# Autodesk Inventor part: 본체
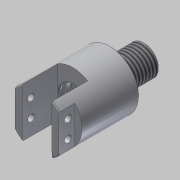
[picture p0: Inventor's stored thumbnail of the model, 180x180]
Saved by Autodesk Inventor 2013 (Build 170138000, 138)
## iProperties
Created: 2019-02
Part Number: 본체
Material: 알루미늄 6061
Document SubType Name: Modeling
Designer: dgall
Density: 2.71 g/cm^3
Mass: 345.865 g
Surface Area: 291.141 cm^2
Volume: 127.625 cm^3
Author: dgall
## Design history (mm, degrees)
sketch "스케치5"
  geometry: C1 r 29 at (0, 0); 1 further point
  constraints: 1 centre point, 1 coincident
  dimensions: "d12" = 58 diameter of C1
extrude "돌출3" new body sketch "스케치5" stored distance "d14" = 74; taper "d15" = 0 deg
sketch "스케치6"
  geometry: L1 (14.984, 24.829)-(15.016, -24.81); L2 (-14.984, -24.829)-(-15.016, 24.81); A1 r 29 centre (0, 0) between (-15.016, 24.81) and (15.016, -24.81) reference; A2 r 29 centre (0, 0) between (-15.016, 24.81) and (15.016, -24.81) reference; A3 r 29 centre (0, 0) between (-14.984, -24.829) and (15.016, -24.81); A4 r 29 centre (0, 0) between (14.984, 24.829) and (-15.016, 24.81)
  constraints: 11 point on circle, 4 end point, 2 centre point, 1 coincident, 1 parallel
  dimensions: "d17" = 30 distance between parallel lines of L1 L2; "d19" = 15 distance from line of A1.centre L2; "d20" = 24.80968 vertical distance of L1.end A1.centre
extrude "돌출4" cut sketch "스케치6" distance "d21" = 36; taper "d22" = 0 deg
node "작업 평면3"
sketch "스케치7"
  geometry: L1 (-37, 24.81)-(-37, -24.829) reference; L2 (-37, 24.81)-(-21, 24.81); L3 (-21, 24.81)-(-21, -24.829); L4 (-21, -24.829)-(-37, -24.829); L5 (-37, -24.829)-(-37, 24.81); 1 further point
  constraints: 8 end point, 2 parallel, 1 horizontal, 1 perpendicular, 1 point on line
  dimensions: "d24" = 16 distance between parallel lines of L3 L1; "d25" = 0 distance from line of L1.start L2; "d26" = 0 distance from line of L1.end L4
extrude "돌출5" cut sketch "스케치7" distance "d27" = 36; taper "d28" = 0 deg
sketch "스케치9"
  geometry: L1 (-1, -24.829)-(-1, 24.81) reference; L2 (-1, -0.01)-(36.922, -0.01); L3 (-1, -0.01)-(-1, 13.99); L4 (-1, 13.99)-(1.65, 13.99); L5 (1.65, 13.99)-(1.65, 16.19); L6 (2.45, 16.99)-(5.55, 16.99); L7 (6.35, 16.19)-(6.35, 13.99); L8 (6.35, 13.99)-(10.65, 13.99); L9 (10.65, 13.99)-(10.65, 16.19); L10 (11.45, 16.99)-(14.55, 16.99); L11 (15.35, 16.19)-(15.35, 13.99); L12 (15.35, 13.99)-(19, 13.99); L13 (19, 13.99)-(19, 15.99); L14 (4, 16.99)-(4, -0.01); L15 (13, 16.99)-(13, -0.01); L16 (19, 15.99)-(26, 15.99); L17 (26, 15.99)-(26, -0.01); A1 r 0.8 centre (2.45, 16.19) between (2.45, 16.99) and (1.65, 16.19); A2 r 0.8 centre (5.55, 16.19) between (6.35, 16.19) and (5.55, 16.99); A3 r 0.8 centre (11.45, 16.19) between (11.45, 16.99) and (10.65, 16.19); A4 r 0.8 centre (14.55, 16.19) between (15.35, 16.19) and (14.55, 16.99); 5 further points
  constraints: 32 end point, 12 point on line, 8 point on circle, 8 tangent, 7 perpendicular, 6 parallel, 4 centre point, 3 midpoint, 2 collinear, 2 equal radius
  dimensions: "d32" = 28 diameter of L4 L2; "d33" = 34 diameter of L6 L2; "d34" = 5 distance between parallel lines of L14 L3; "d35" = 4.7 distance between parallel lines of L7 L5; "d36" = 28 diameter of L8 L2; "d37" = 4.7 distance between parallel lines of L11 L9; "d38" = 9 distance between parallel lines of L15 L14; "d39" = 34 diameter of L10 L2; "d40" = 28 diameter of L12 L2; "d41" = 32 diameter of L16 L2; "d42" = 7 distance between parallel lines of L17 L13; "d44" = 20 distance between parallel lines of L13 L1; "d70" = 0.8 radius of A1; "d71" = 0.8 radius of A2
revolve "회전1" sketch "스케치9" stored, may be unused: angle "d45" = 90 deg
sketch "스케치10"
  geometry: C1 r 29 at (0, 0) reference; C2 r 14 at (0, 0)
  constraints: 1 centre point, 1 coincident
  dimensions: "d46" = 28 diameter of C2
extrude "돌출6" join sketch "스케치10" distance "d48" = 5; taper "d49" = 0 deg
sketch "스케치11"
  geometry: C1 r 14 at (0, 0) reference; C2 r 15 at (0, 0)
  constraints: 1 centre point, 1 coincident
  dimensions: "d50" = 30 diameter of C2
extrude "돌출7" join sketch "스케치11" distance "d52" = 29; taper "d53" = 0 deg
sketch "스케치12"
  geometry: C1 r 15 at (0, 0) reference; C2 r 7 at (0, 0)
  constraints: 1 centre point, 1 coincident
  dimensions: "d54" = 14 diameter of C2
extrude "돌출8" cut sketch "스케치12" distance "d56" = 22; taper "d57" = 0 deg
sketch "스케치13"
  geometry: C1 r 7 at (0, 0) reference; C2 r 4 at (0, 0)
  constraints: 1 centre point, 1 coincident
  dimensions: "d58" = 8 diameter of C2
extrude "돌출9" cut sketch "스케치13" stored distance "d60" = 22; taper "d61" = 0 deg
chamfer "모따기1" distance "d62" = 1; stored, may be unused: second distance "d63" = 2, angle "d64" = 45 deg
chamfer "모따기2" distance "d65" = 1; stored, may be unused: second distance "d66" = 2, angle "d67" = 45 deg
chamfer "모따기3" distance "d72" = 1; stored, may be unused: second distance "d73" = 2, angle "d74" = 45 deg
feature "스레드1" dims "d75" = 10, "d76" = 0
chamfer "모따기4" distance "d77" = 1; stored, may be unused: second distance "d78" = 2, angle "d79" = 45 deg
chamfer "모따기5" distance "d80" = 1; stored, may be unused: second distance "d81" = 2, angle "d82" = 45 deg
feature "스레드2" dims "d83" = 18, "d84" = 0
chamfer "모따기6" distance "d85" = 1; stored, may be unused: second distance "d86" = 2, angle "d87" = 45 deg
sketch "스케치14"
  geometry: L1 (36.215, -16)-(1.574, -16) reference; C1 r 3.5 at (9.894, -7); C2 r 3.5 at (27.894, -7); 1 further point
  constraints: 2 centre point
  dimensions: "d88" = 9 distance from line of C1.centre L1; "d89" = 9 distance from line of C2.centre L1; "d90" = 9 horizontal distance of point (18.894, 21) C1.centre; "d91" = 9 horizontal distance of C2.centre point (18.894, 21); "d92" = 7 diameter of C1; "d93" = 7 diameter of C2
extrude "돌출10" cut sketch "스케치14" stored distance "d94" = 7; taper "d95" = 0 deg
sketch "스케치15"
  geometry: L1 (17.321, -37)-(-17.321, -37) reference; C1 r 3.5 at (9, -28); C2 r 3.5 at (-9, -28) reference; C3 r 3.5 at (-9, -28); 1 further point
  constraints: 2 centre point, 1 coincident
  dimensions: "d96" = 7 diameter of C3; "d98" = 7 diameter of C1; "d99" = 18 distance of C3.centre C1.centre; "d100" = 9 distance from line of L1 C1.centre
extrude "돌출11" cut sketch "스케치15" stored distance "d101" = 7; taper "d102" = 0 deg
node "작업 평면4"
sketch "스케치16"
  geometry: L1 (9, -5)-(-31, -5); L2 (-31, -5)-(-31, 5); L3 (-31, 5)-(9, 5); L4 (9, 5)-(9, -5); L5 (9, -5)-(-31, 5); L6 (-31, -5)-(9, 5); L7 (9, 0)-(-31, 0); L8 (-11, -5)-(-11, 5); L9 (-36, 29)-(-36, -29) reference; 2 further points
  constraints: 16 end point, 6 midpoint, 2 parallel, 1 horizontal, 1 perpendicular
  dimensions: "d104" = 40 distance between parallel lines of L2 L4; "d106" = 10 distance between parallel lines of L3 L1; "d107" = 0 distance from line of point (0, 0) L7; "d108" = 5 distance between parallel lines of L9 L2
extrude "돌출12" join sketch "스케치16" stored distance "d109" = 7; taper "d110" = 0 deg
sketch "스케치17"
  geometry: L1 (5, -9)-(-5, -9) reference; L2 (-1.991, -5.592)-(-1.991, 27.592); L3 (-1.991, 27.592)-(1.991, 27.592); L4 (1.991, 27.592)-(1.991, -5.592); L5 (1.991, -5.592)-(-1.991, -5.592); L6 (0, -5.592)-(0, 27.592); L7 (-1.991, 11)-(1.991, 11); 1 further point
  constraints: 4 end point, 4 midpoint, 2 other
  dimensions: "d111" = 0 distance from line of point (0, 0) L6; "d112" = 20 distance between parallel lines of L7 L1
extrude "돌출13" join sketch "스케치17" distance "d113" = 0.5; taper "d114" = 0 deg
node "솔리드2"
mirror "대칭1"
other parameters: "d23" = 22
